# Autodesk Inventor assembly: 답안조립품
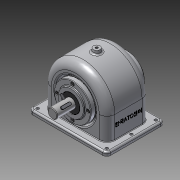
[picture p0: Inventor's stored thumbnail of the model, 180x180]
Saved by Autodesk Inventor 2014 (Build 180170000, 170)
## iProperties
Created: 2015-09
Part Number: 답안조립품
Document SubType Name: Assembly
Designer: Administrator
Author: Administrator
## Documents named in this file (14)
- C:\Users\Administrator\Desktop\450907V1048\답안조립품.iam
- C:\Users\Administrator\Desktop\450907V1048\1-본체.ipt
- C:\Users\Administrator\Desktop\450907V1048\V-벨트풀리.ipt
- C:\Users\Administrator\Desktop\450907V1048\뒤커버.ipt
- C:\Users\Administrator\Desktop\450907V1048\멈춤나사 - M4x10.ipt
- C:\Users\Administrator\Desktop\450907V1048\베어링 6203.ipt
- C:\Users\Administrator\Desktop\450907V1048\볼트 M3 x 8.ipt
- C:\Users\Administrator\Desktop\450907V1048\볼트 M3 x 10.ipt
- C:\Users\Administrator\Desktop\450907V1048\스퍼기어.ipt
- C:\Users\Administrator\Desktop\450907V1048\앞커버.ipt
- C:\Users\Administrator\Desktop\450907V1048\오일 실 17 32 8.ipt
- C:\Users\Administrator\Desktop\450907V1048\축.ipt
- C:\Users\Administrator\Desktop\450907V1048\키 - 5 x 5 x 18.ipt
- C:\Users\Administrator\Desktop\450907V1048\키 - 6 x 6 x 22.ipt
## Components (10 placed, 4 different names)
1. 1-본체:1 — 각도:1, 각도:2, 각도:3, 각도:4, 각도:5, 각도:6, 각도:7, 각도:8
2. V-벨트풀리:1
3. ISO 4762 M3 x 8:1 — 각도:1
4. ISO 4762 M3 x 10:1 — 각도:8
5. ISO 4762 M3 x 8:2 — 각도:3
6. ISO 4762 M3 x 8:3 — 각도:4
7. ISO 4762 M3 x 8:4 — 각도:2
8. ISO 4762 M3 x 10:2 — 각도:7
9. ISO 4762 M3 x 10:3 — 각도:6
10. ISO 4762 M3 x 10:4 — 각도:5
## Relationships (8: Angle 8)
- 각도:1 [Angle]: 1-본체:1 ↔ ISO 4762 M3 x 8:1
- 각도:2 [Angle]: 1-본체:1 ↔ ISO 4762 M3 x 8:4
- 각도:3 [Angle]: 1-본체:1 ↔ ISO 4762 M3 x 8:2
- 각도:4 [Angle]: 1-본체:1 ↔ ISO 4762 M3 x 8:3
- 각도:5 [Angle]: 1-본체:1 ↔ ISO 4762 M3 x 10:4
- 각도:6 [Angle]: 1-본체:1 ↔ ISO 4762 M3 x 10:3
- 각도:7 [Angle]: 1-본체:1 ↔ ISO 4762 M3 x 10:2
- 각도:8 [Angle]: 1-본체:1 ↔ ISO 4762 M3 x 10:1
